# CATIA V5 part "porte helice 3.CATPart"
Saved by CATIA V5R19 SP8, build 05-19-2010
Part number: porte helice 3
Bounding box of the stored display mesh (mm): x -20 to 20, y -50 to 180, z -20 to 20
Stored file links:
  G:\EU_thinkMotion\CFAO_2010\MMS_groupe2\MMS_groupe2\A reprendre\splanchenault\Planchenault\porte helice 3.CATPart
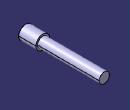
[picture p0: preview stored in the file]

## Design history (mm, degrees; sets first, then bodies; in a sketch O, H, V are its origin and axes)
Body1 (main body)
  Sketch1 on zx-plane, origin (0, 0, 0), H (-1, 0, 0), V (0, 0, 1)
    circle A1 centre (0, 0) radius 15
    radius A1 = 15
  Pad1: profile Sketch1, direction (0, 1, 0), length 180
  Sketch2 on start face of Pad1, origin (0, 0, 0), H (1, 0, 0), V (0, 0, 1)
    circle A1 centre (0, 0) radius 20
    radius A1 = 20
  Pad2: profile Sketch2, direction (0, -1, 0), length 50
